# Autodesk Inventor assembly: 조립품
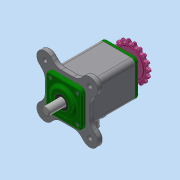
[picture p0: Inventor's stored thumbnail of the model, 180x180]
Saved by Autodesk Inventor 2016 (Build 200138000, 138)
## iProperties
Created: 2019-11
Part Number: 조립품
Material: 일반
Document SubType Name: Assembly
Designer: user
Author: user
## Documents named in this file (11)
- C:\Users\user\Desktop\491109V1009\조립품.iam
- C:\Users\user\Desktop\491109V1009\베어링 6203.ipt
- C:\Users\user\Desktop\491109V1009\본체.ipt
- C:\Users\user\Desktop\491109V1009\볼트 M4.ipt
- C:\Users\user\Desktop\491109V1009\부시.ipt
- C:\Users\user\Desktop\491109V1009\스프로킷.ipt
- C:\Users\user\Desktop\491109V1009\슬라이더.ipt
- C:\Users\user\Desktop\491109V1009\오일 실.ipt
- C:\Users\user\Desktop\491109V1009\커버.ipt
- C:\Users\user\Desktop\491109V1009\키 4 x 4 x 14.ipt
- C:\Users\user\Desktop\491109V1009\편심축.ipt
